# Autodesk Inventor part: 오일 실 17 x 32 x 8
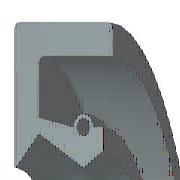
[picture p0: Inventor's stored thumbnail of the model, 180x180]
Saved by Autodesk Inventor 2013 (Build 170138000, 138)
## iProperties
Created: 2012-02
Part Number: 오일 실 17 x 32 x 8
Material: 고무
Description: 샤프트 실 링
Document SubType Name: Modeling
Standard: JIS B 2402
Designer: mdu-01
Standards Organization: JIS
Language: ko-KR
Size Designation: D 17 x 32 x 8
Categories: <MemberInstance><Categories><Category DisplayName="샤프트 부품" InternalName="7f7aeb1f-a693-4053-b835-cee3144e0d98" Mnemonic="SHFT"><Category DisplayName="실링" Intern
Density: 0.93 g/cm^3
IsCustomPart: 1
Author: mdu-01
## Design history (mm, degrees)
revolve "본체" stored, may be unused: angle "d17" = 90 deg
revolve "스프링1" stored, may be unused: angle "d18" = 90 deg
body "Solid1"
sketch "스케치1"
  geometry: L1 (0, 16)-(8, 16); L2 (8, 14.25)-(1.75, 14.25); L3 (1.75, 10.25)-(4.9, 8.5); L4 (4.9, 8.5)-(0, 8.5); L5 (0, 0)-(9.586, 0) reference; L6 (4.9, 8.5)-(6.3, 9.375); L7 (0, 18)-(0, -3) reference; L8 (-1.941, 0)-(11.507, 0) reference; L9 (4.2, 10.6)-(1.75, 11.21); L10 (1.75, 11.21)-(1.75, 14.25); L11 (0, 16)-(0, 8.588); L12 (4.9, 8.5)-(0, 8.5); L13 (1.75, 10.25)-(0.152, 8.528); L14 (8, 16)-(8, 14.25); L15 (5.6, 10.6)-(6.3, 10.6); L16 (6.3, 10.6)-(6.3, 9.375); C1 r 0.455 at (4.9, 10.6); A1 r 0.7 centre (4.9, 10.6) between (5.6, 10.6) and (4.2, 10.6); A2 r 0.088 centre (0.088, 8.588) between (0, 8.588) and (0.152, 8.528); 1 further point
  constraints: 28 end point, 5 horizontal alignment, 5 point on line, 4 point on circle, 4 vertical alignment, 3 centre point, 3 tangent, 2 collinear, 2 horizontal, 2 perpendicular, 1 coincident, 1 parallel
  dimensions: "d0" = 32 diameter of L1 L5 (= SD2); "d1" = 1.75 distance of L1.end L2.start (= SD); "d2" = 0.91 diameter of C1 (= SPDI); "d3" = 1.4 diameter of A1 (= SPDA); "d4" = 17 diameter of L3.end L5 (= NND); "d5" = 20.5 diameter of L3.start L5 (= TKDM); "d7" = 22.42 diameter of L9.end L5 (= TKDM + 0.24 x SWDT); "d8" = 1.75 distance between parallel lines of L11 L10 (= SD); "d9" = 4.9 distance from line of L11 C1.centre (= SPDST); "d10" = 21.2 diameter of C1.centre L5 (= HLDM); "d11" = 0.0875 radius of A2 (= 0.25 x LAB); "d12" = 6.3 distance between parallel lines of L11 L16 (= SDI); "d13" = 18.75 diameter of L6.end L5 (= ABDM); "d14" = 8 distance from line of L11 L1.end (= SWDT)
fillet "모깎기1" dims "d6" = 0.3 (= RR)
other parameters: "SD2" = 32 [user parameter; used in 1 equation term], "SWDT" = 8 [user parameter; used in 2 equation terms], "RR" = 0.3 [user parameter; used in 1 equation term], "SD" = 1.75 [user parameter; used in 2 equation terms], "NND" = 17 [user parameter; used in 1 equation term], "SPDA" = 1.4 [user parameter; used in 1 equation term], "SPDI" = 0.91 [user parameter; used in 1 equation term], "TKDM" = 20.5 [user parameter; used in 2 equation terms], "HLDM" = 21.2 [user parameter; used in 1 equation term], "ABDM" = 18.75 [user parameter; used in 1 equation term], "SDI" = 6.3 [user parameter; used in 1 equation term], "SPDST" = 4.9 [user parameter; used in 1 equation term], "LAB" = 0.35 [user parameter; used in 1 equation term], "d15" = 0, "d16" = 0, "d19" = 0
